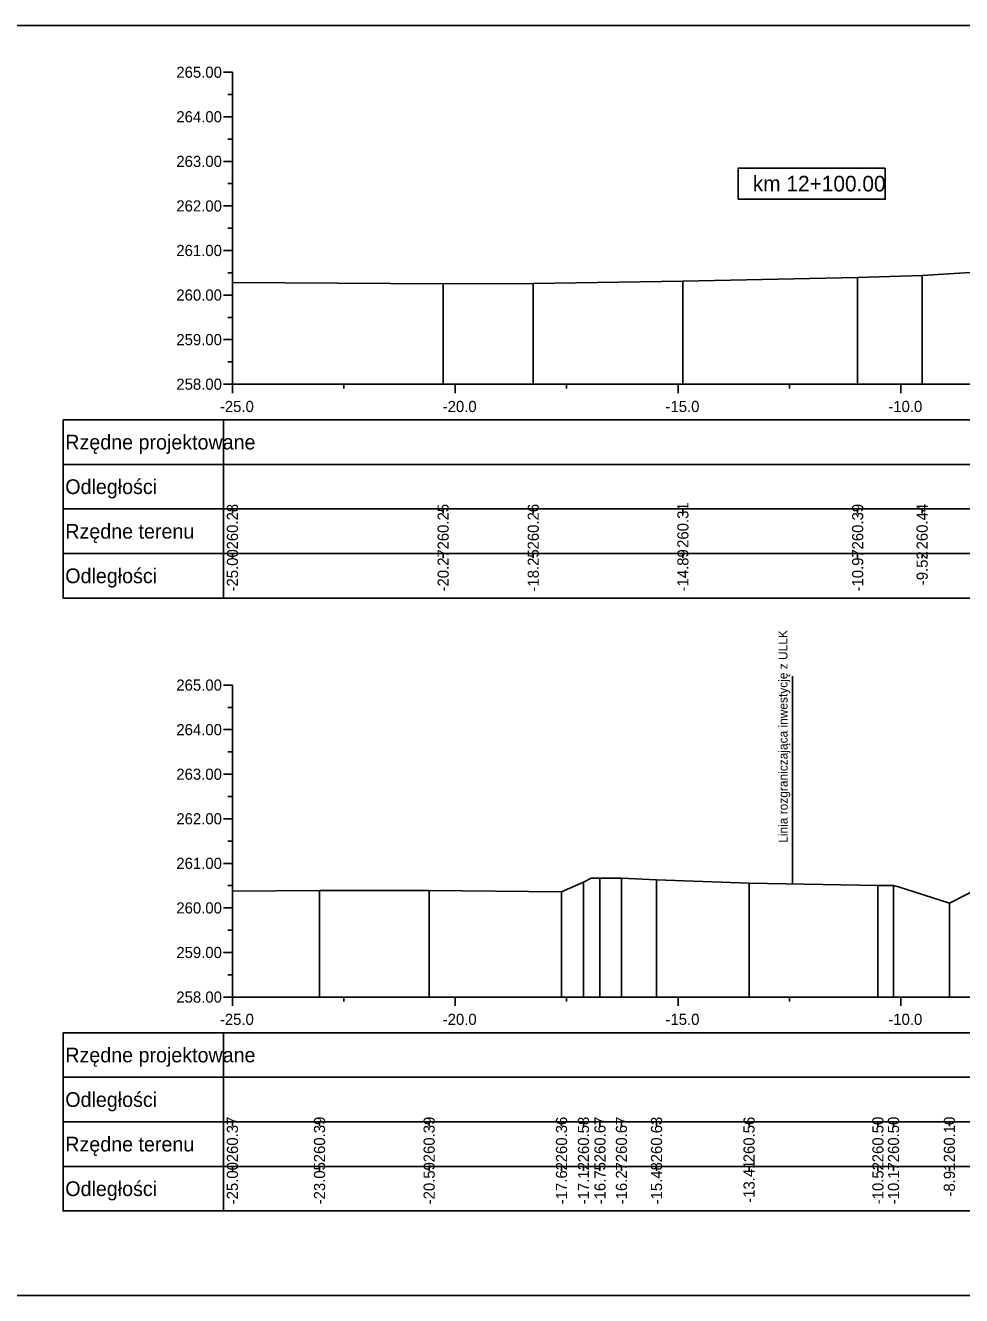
# Model space of a CAD drawing. Extents: x 6516023 to 6560129, y 5513077 to 5529206.
# Drawn here: x 6516921.76 to 6516942.77, y 5513396.29 to 5513424.79 of the extents above; entities that cross this region are included whole.
import ezdxf

# ---------------------------------------------------------------- set-up
doc = ezdxf.new("R2010")
doc.units = 0
for name, color, linetype in [('TOR_PRZEK_P-tabelka istniejace', 7, 'Continuous'), ('TOR_PRZEK_P-tabelka projektowane', 7, 'Continuous'), ('TOR_PRZEK_P-teren istniejacy', 7, 'Continuous'), ('TOR_PRZEK_P-uklad odniesienia', 7, 'Continuous'), ('TOR_PS_T-granica PKP-projektowana', 7, 'Continuous'), ('TOR_RAMKI-ramka+tabelka 1', 7, 'Continuous')]:
    doc.layers.add(name, color=color, linetype=linetype)

msp = doc.modelspace()

# ---------------------------------------------------------------- linework, layer by layer
at = {"layer": 'TOR_PRZEK_P-tabelka istniejace'}
for p, q in [((6516922.61, 5513413.939), (6516922.61, 5513411.939)), ((6516926.21, 5513413.939), (6516926.21, 5513411.939)), ((6516926.41, 5513413.839), (6516926.41, 5513413.939)), ((6516931.139, 5513413.839), (6516931.139, 5513413.939)), ((6516933.161, 5513413.839), (6516933.161, 5513413.939)), ((6516936.519, 5513413.839), (6516936.519, 5513413.939)), ((6516940.441, 5513413.839), (6516940.441, 5513413.939)), ((6516941.888, 5513413.839), (6516941.888, 5513413.939)), ((6516922.61, 5513412.939), (6516976.41, 5513412.939)), ((6516926.41, 5513412.839), (6516926.41, 5513412.939)), ((6516931.139, 5513412.839), (6516931.139, 5513412.939)), ((6516933.161, 5513412.839), (6516933.161, 5513412.939)), ((6516936.519, 5513412.839), (6516936.519, 5513412.939)), ((6516940.441, 5513412.839), (6516940.441, 5513412.939)), ((6516941.888, 5513412.839), (6516941.888, 5513412.939)), ((6516922.61, 5513400.188), (6516922.61, 5513398.188)), ((6516926.21, 5513400.188), (6516926.21, 5513398.188)), ((6516926.41, 5513400.088), (6516926.41, 5513400.188)), ((6516928.365, 5513400.088), (6516928.365, 5513400.188)), ((6516930.825, 5513400.088), (6516930.825, 5513400.188)), ((6516933.795, 5513400.088), (6516933.795, 5513400.188)), ((6516934.288, 5513400.088), (6516934.288, 5513400.188)), ((6516934.659, 5513400.088), (6516934.659, 5513400.188)), ((6516935.14, 5513400.088), (6516935.14, 5513400.188)), ((6516935.927, 5513400.088), (6516935.927, 5513400.188)), ((6516938.004, 5513400.088), (6516938.004, 5513400.188)), ((6516940.895, 5513400.088), (6516940.895, 5513400.188)), ((6516941.245, 5513400.088), (6516941.245, 5513400.188)), ((6516942.499, 5513400.088), (6516942.499, 5513400.188)), ((6516922.61, 5513399.188), (6516976.41, 5513399.188)), ((6516926.41, 5513399.088), (6516926.41, 5513399.188)), ((6516928.365, 5513399.088), (6516928.365, 5513399.188)), ((6516930.825, 5513399.088), (6516930.825, 5513399.188)), ((6516933.795, 5513399.088), (6516933.795, 5513399.188)), ((6516934.288, 5513399.088), (6516934.288, 5513399.188)), ((6516934.659, 5513399.088), (6516934.659, 5513399.188)), ((6516935.14, 5513399.088), (6516935.14, 5513399.188)), ((6516935.927, 5513399.088), (6516935.927, 5513399.188)), ((6516938.004, 5513399.088), (6516938.004, 5513399.188)), ((6516940.895, 5513399.088), (6516940.895, 5513399.188)), ((6516941.245, 5513399.088), (6516941.245, 5513399.188)), ((6516942.499, 5513399.088), (6516942.499, 5513399.188))]:
    msp.add_line(p, q, dxfattribs=at)
for points in [[(6516936.519, 5513419.051), (6516936.519, 5513416.939), (6516936.519, 5513416.809), (6516936.519, 5513416.739)], [(6516940.441, 5513419.13), (6516940.441, 5513416.939), (6516940.441, 5513416.809), (6516940.441, 5513416.739)], [(6516941.888, 5513419.176), (6516941.888, 5513416.939), (6516941.888, 5513416.809), (6516941.888, 5513416.739)], [(6516926.41, 5513419.02), (6516926.41, 5513416.939), (6516926.41, 5513416.809), (6516926.41, 5513416.739)], [(6516931.139, 5513418.989), (6516931.139, 5513416.939), (6516931.139, 5513416.809), (6516931.139, 5513416.739)], [(6516933.161, 5513418.996), (6516933.161, 5513416.939), (6516933.161, 5513416.809), (6516933.161, 5513416.739)], [(6516928.365, 5513405.377), (6516928.365, 5513403.188), (6516928.365, 5513403.058), (6516928.365, 5513402.988)], [(6516930.825, 5513405.378), (6516930.825, 5513403.188), (6516930.825, 5513403.058), (6516930.825, 5513402.988)], [(6516934.288, 5513405.569), (6516934.288, 5513403.188), (6516934.288, 5513403.058), (6516934.288, 5513402.988)], [(6516934.659, 5513405.655), (6516934.659, 5513403.188), (6516934.659, 5513403.058), (6516934.659, 5513402.988)], [(6516935.14, 5513405.654), (6516935.14, 5513403.188), (6516935.14, 5513403.058), (6516935.14, 5513402.988)], [(6516935.927, 5513405.621), (6516935.927, 5513403.188), (6516935.927, 5513403.058), (6516935.927, 5513402.988)], [(6516938.004, 5513405.544), (6516938.004, 5513403.188), (6516938.004, 5513403.058), (6516938.004, 5513402.988)], [(6516940.895, 5513405.493), (6516940.895, 5513403.188), (6516940.895, 5513403.058), (6516940.895, 5513402.988)], [(6516941.245, 5513405.488), (6516941.245, 5513403.188), (6516941.245, 5513403.058), (6516941.245, 5513402.988)], [(6516926.41, 5513405.361), (6516926.41, 5513403.188), (6516926.41, 5513403.058), (6516926.41, 5513402.988)], [(6516933.795, 5513405.352), (6516933.795, 5513403.188), (6516933.795, 5513403.058), (6516933.795, 5513402.988)], [(6516942.499, 5513405.091), (6516942.499, 5513403.188), (6516942.499, 5513403.058), (6516942.499, 5513402.988)]]:
    msp.add_lwpolyline(points, dxfattribs=at)
for points in [[(6516922.61, 5513413.939), (6516922.61, 5513411.939), (6516976.41, 5513411.939), (6516976.41, 5513413.939)], [(6516922.61, 5513400.188), (6516922.61, 5513398.188), (6516976.41, 5513398.188), (6516976.41, 5513400.188)]]:
    msp.add_lwpolyline(points, close=True, dxfattribs=at)
at = {"layer": 'TOR_PRZEK_P-tabelka projektowane'}
for p, q in [((6516922.61, 5513415.939), (6516922.61, 5513413.939)), ((6516926.21, 5513415.939), (6516926.21, 5513413.939)), ((6516922.61, 5513414.939), (6516976.41, 5513414.939)), ((6516922.61, 5513402.188), (6516922.61, 5513400.188)), ((6516926.21, 5513402.188), (6516926.21, 5513400.188)), ((6516922.61, 5513401.188), (6516976.41, 5513401.188))]:
    msp.add_line(p, q, dxfattribs=at)
for points in [[(6516922.61, 5513415.939), (6516922.61, 5513413.939), (6516976.41, 5513413.939), (6516976.41, 5513415.939)], [(6516922.61, 5513402.188), (6516922.61, 5513400.188), (6516976.41, 5513400.188), (6516976.41, 5513402.188)]]:
    msp.add_lwpolyline(points, close=True, dxfattribs=at)
at = {"layer": 'TOR_PRZEK_P-teren istniejacy'}
for points in [[(6516926.41, 5513419.02), (6516931.139, 5513418.989), (6516933.161, 5513418.996), (6516936.519, 5513419.051), (6516940.441, 5513419.13), (6516941.888, 5513419.176), (6516943.088, 5513419.249)], [(6516926.41, 5513405.361), (6516928.365, 5513405.377), (6516930.825, 5513405.378), (6516933.795, 5513405.352), (6516934.288, 5513405.569), (6516934.46, 5513405.655), (6516934.659, 5513405.655), (6516935.14, 5513405.654), (6516935.927, 5513405.621), (6516938.004, 5513405.544), (6516940.895, 5513405.493), (6516941.245, 5513405.488), (6516941.357, 5513405.461), (6516942.499, 5513405.091), (6516943.911, 5513405.81)]]:
    msp.add_lwpolyline(points, dxfattribs=at)
at = {"layer": 'TOR_PRZEK_P-uklad odniesienia'}
for p, q in [((6516926.21, 5513423.739), (6516926.41, 5513423.739)), ((6516926.41, 5513423.739), (6516926.41, 5513416.739)), ((6516926.31, 5513423.239), (6516926.41, 5513423.239)), ((6516926.21, 5513422.739), (6516926.41, 5513422.739)), ((6516926.31, 5513422.239), (6516926.41, 5513422.239)), ((6516926.21, 5513421.739), (6516926.41, 5513421.739)), ((6516926.31, 5513421.239), (6516926.41, 5513421.239)), ((6516926.21, 5513420.739), (6516926.41, 5513420.739)), ((6516926.31, 5513420.239), (6516926.41, 5513420.239)), ((6516926.21, 5513419.739), (6516926.41, 5513419.739)), ((6516926.31, 5513419.239), (6516926.41, 5513419.239)), ((6516926.21, 5513418.739), (6516926.41, 5513418.739)), ((6516926.31, 5513418.239), (6516926.41, 5513418.239)), ((6516926.21, 5513417.739), (6516926.41, 5513417.739)), ((6516926.31, 5513417.239), (6516926.41, 5513417.239)), ((6516926.21, 5513416.739), (6516926.41, 5513416.739)), ((6516926.41, 5513416.739), (6516976.41, 5513416.739)), ((6516926.41, 5513416.539), (6516926.41, 5513416.739)), ((6516928.91, 5513416.639), (6516928.91, 5513416.739)), ((6516931.41, 5513416.539), (6516931.41, 5513416.739)), ((6516933.91, 5513416.639), (6516933.91, 5513416.739)), ((6516936.41, 5513416.539), (6516936.41, 5513416.739)), ((6516938.91, 5513416.639), (6516938.91, 5513416.739)), ((6516941.41, 5513416.539), (6516941.41, 5513416.739)), ((6516926.21, 5513409.988), (6516926.41, 5513409.988)), ((6516926.41, 5513409.988), (6516926.41, 5513402.988)), ((6516926.31, 5513409.488), (6516926.41, 5513409.488)), ((6516926.21, 5513408.988), (6516926.41, 5513408.988)), ((6516926.31, 5513408.488), (6516926.41, 5513408.488)), ((6516926.21, 5513407.988), (6516926.41, 5513407.988)), ((6516926.31, 5513407.488), (6516926.41, 5513407.488)), ((6516926.21, 5513406.988), (6516926.41, 5513406.988)), ((6516926.31, 5513406.488), (6516926.41, 5513406.488)), ((6516926.21, 5513405.988), (6516926.41, 5513405.988)), ((6516926.31, 5513405.488), (6516926.41, 5513405.488)), ((6516926.21, 5513404.988), (6516926.41, 5513404.988)), ((6516926.31, 5513404.488), (6516926.41, 5513404.488)), ((6516926.21, 5513403.988), (6516926.41, 5513403.988)), ((6516926.31, 5513403.488), (6516926.41, 5513403.488)), ((6516926.21, 5513402.988), (6516926.41, 5513402.988)), ((6516926.41, 5513402.988), (6516976.41, 5513402.988)), ((6516926.41, 5513402.788), (6516926.41, 5513402.988)), ((6516928.91, 5513402.888), (6516928.91, 5513402.988)), ((6516931.41, 5513402.788), (6516931.41, 5513402.988)), ((6516933.91, 5513402.888), (6516933.91, 5513402.988)), ((6516936.41, 5513402.788), (6516936.41, 5513402.988)), ((6516938.91, 5513402.888), (6516938.91, 5513402.988)), ((6516941.41, 5513402.788), (6516941.41, 5513402.988))]:
    msp.add_line(p, q, dxfattribs=at)
msp.add_lwpolyline([(6516941.06, 5513421.589), (6516937.76, 5513421.589), (6516937.76, 5513420.889), (6516941.06, 5513420.889)], close=True, dxfattribs=at)
at = {"layer": 'TOR_PS_T-granica PKP-projektowana'}
msp.add_line((6516938.98, 5513405.527), (6516938.98, 5513410.185), dxfattribs=at)
at = {"layer": 'TOR_RAMKI-ramka+tabelka 1'}
msp.add_lwpolyline([(6516805.96, 5513424.789), (6517053.46, 5513424.789), (6517053.46, 5513396.289), (6516805.96, 5513396.289)], close=True, dxfattribs=at)

# ---------------------------------------------------------------- texts
at = {"layer": 'TOR_PRZEK_P-tabelka istniejace'}
for s, p in [('260.28', (6516926.535, 5513413.031)), ('260.25', (6516931.264, 5513413.03)), ('260.26', (6516933.286, 5513413.031)), ('260.31', (6516936.644, 5513413.066)), ('260.39', (6516940.566, 5513413.031)), ('260.44', (6516942.013, 5513413.032)), ('-25.00', (6516926.535, 5513412.088)), ('-20.27', (6516931.264, 5513412.088)), ('-18.25', (6516933.286, 5513412.086)), ('-14.89', (6516936.644, 5513412.088)), ('-10.97', (6516940.566, 5513412.088)), ('-9.52', (6516942.013, 5513412.229)), ('260.37', (6516926.535, 5513399.281)), ('260.39', (6516928.49, 5513399.281)), ('260.39', (6516930.95, 5513399.281)), ('260.36', (6516933.92, 5513399.28)), ('260.58', (6516934.413, 5513399.28)), ('260.67', (6516934.784, 5513399.281)), ('260.67', (6516935.265, 5513399.281)), ('260.63', (6516936.052, 5513399.28)), ('260.56', (6516938.129, 5513399.28)), ('260.50', (6516941.02, 5513399.281)), ('260.50', (6516941.37, 5513399.281)), ('260.10', (6516942.624, 5513399.281)), ('-25.00', (6516926.535, 5513398.337)), ('-23.05', (6516928.49, 5513398.336)), ('-20.59', (6516930.95, 5513398.337)), ('-17.62', (6516933.92, 5513398.338)), ('-17.12', (6516934.413, 5513398.338)), ('-16.75', (6516934.784, 5513398.336)), ('-16.27', (6516935.265, 5513398.337)), ('-15.48', (6516936.052, 5513398.336)), ('-13.41', (6516938.129, 5513398.371)), ('-10.52', (6516941.02, 5513398.338)), ('-10.17', (6516941.37, 5513398.337)), ('-8.91', (6516942.624, 5513398.511))]:
    msp.add_text(s, height=0.25, rotation=90, dxfattribs=at).set_placement(p)
for s, p in [('Rzędne terenu', (6516922.66, 5513413.274)), ('Odległości', (6516922.66, 5513412.274)), ('Rzędne terenu', (6516922.66, 5513399.523)), ('Odległości', (6516922.66, 5513398.523))]:
    msp.add_text(s, height=0.33, dxfattribs=at).set_placement(p)
at = {"layer": 'TOR_PRZEK_P-tabelka projektowane'}
for s, p in [('Rzędne projektowane', (6516922.66, 5513415.274)), ('Odległości', (6516922.66, 5513414.274)), ('Rzędne projektowane', (6516922.66, 5513401.523)), ('Odległości', (6516922.66, 5513400.523))]:
    msp.add_text(s, height=0.33, dxfattribs=at).set_placement(p)
at = {"layer": 'TOR_PRZEK_P-uklad odniesienia'}
for s, height, p in [('265.00', 0.25, (6516925.152, 5513423.614)), ('264.00', 0.25, (6516925.152, 5513422.614)), ('263.00', 0.25, (6516925.152, 5513421.614)), ('km 12+100.00', 0.35, (6516938.088, 5513421.064)), ('262.00', 0.25, (6516925.152, 5513420.614)), ('261.00', 0.25, (6516925.152, 5513419.614)), ('260.00', 0.25, (6516925.152, 5513418.614)), ('259.00', 0.25, (6516925.152, 5513417.614)), ('258.00', 0.25, (6516925.152, 5513416.614)), ('-', 0.0001, (6516926.41, 5513416.739)), ('-25.0', 0.25, (6516926.129, 5513416.114)), ('-20.0', 0.25, (6516931.129, 5513416.114)), ('-15.0', 0.25, (6516936.129, 5513416.114)), ('-10.0', 0.25, (6516941.129, 5513416.114)), ('265.00', 0.25, (6516925.152, 5513409.863)), ('264.00', 0.25, (6516925.152, 5513408.863)), ('263.00', 0.25, (6516925.152, 5513407.863)), ('262.00', 0.25, (6516925.152, 5513406.863)), ('261.00', 0.25, (6516925.152, 5513405.863)), ('260.00', 0.25, (6516925.152, 5513404.863)), ('259.00', 0.25, (6516925.152, 5513403.863)), ('258.00', 0.25, (6516925.152, 5513402.863)), ('-', 0.0001, (6516926.41, 5513402.988)), ('-25.0', 0.25, (6516926.129, 5513402.363)), ('-20.0', 0.25, (6516931.129, 5513402.363)), ('-15.0', 0.25, (6516936.129, 5513402.363)), ('-10.0', 0.25, (6516941.129, 5513402.363))]:
    msp.add_text(s, height=height, dxfattribs=at).set_placement(p)
at = {"layer": 'TOR_PS_T-granica PKP-projektowana'}
msp.add_text('Linia rozgraniczająca inwestycję z ULLK', height=0.2, rotation=90.0511, dxfattribs=at).set_placement((6516938.87, 5513406.449))

doc.saveas('drawing.dxf')
